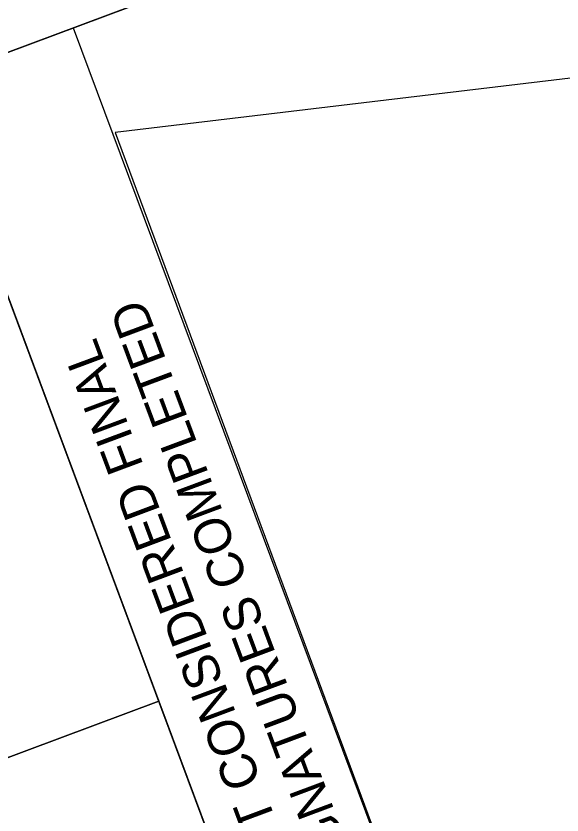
# Model space of a CAD drawing. Extents: x 477774 to 479389, y 493760 to 495720.
# Drawn here: x 477955.2 to 478037.9, y 495270.7 to 495391.6 of the extents above; entities that cross this region are included whole.
import ezdxf

# ---------------------------------------------------------------- set-up
doc = ezdxf.new("R2010")
doc.units = 0
for name, color, linetype in [('Sheet Clip Boundary CELL', 7, 'Continuous'), ('Sheet Plan CELL', 7, 'Continuous'), ('Sheet Sticker Exception Certification CELL', 7, 'Continuous')]:
    doc.layers.add(name, color=color, linetype=linetype)

msp = doc.modelspace()

# ---------------------------------------------------------------- linework, layer by layer
at = {"layer": 'Sheet Clip Boundary CELL'}
msp.add_lwpolyline([(478513.92, 493994.03), (478682.91, 494117.93), (478968.98, 494336.48), (479221.09, 494528.01), (478936.81, 495289.59), (478873.03, 495265.78), (478780.85, 495512.74), (478769.67, 495508.56), (478559.23, 495460.97), (478204.1, 495401.95), (477970.22, 495374), (478033.83, 495202.43), (477871.23, 495141.73), (478325.87, 493923.83)], close=True, dxfattribs=at)
at = {"layer": 'Sheet Plan CELL'}
msp.add_line((477871.45, 495248.6), (477976.8, 495287.94), dxfattribs=at)
for points in [[(477801.28, 495329.17), (478325.84, 493923.85), (479309.54, 494291.03), (478784.99, 495696.34)], [(479309.54, 494291.03), (478325.87, 493923.83), (477871.23, 495141.73), (478011.81, 495194.22), (477941.87, 495381.63), (478784.99, 495696.34)], [(477871.45, 495248.6), (477836.47, 495342.27), (477941.87, 495381.63), (477976.85, 495287.95)], [(477906.43, 495154.87), (477871.45, 495248.6), (477976.85, 495287.95), (478011.81, 495194.22)]]:
    msp.add_lwpolyline(points, close=True, dxfattribs=at)
at = {"layer": 'Sheet Sticker Exception Certification CELL'}
for p, q in [((477941.87, 495381.63), (477963.89, 495389.85)), ((477941.87, 495381.63), (477963.89, 495389.85)), ((477963.88, 495389.84), (478033.83, 495202.43)), ((477963.88, 495389.84), (478033.83, 495202.43)), ((478011.81, 495194.22), (477941.86, 495381.62)), ((478011.81, 495194.22), (477941.86, 495381.62))]:
    msp.add_line(p, q, dxfattribs=at)

# ---------------------------------------------------------------- texts
for s, p in [('UNLESS ALL SIGNATURES COMPLETED', (478024.16, 495215.9)), ('UNLESS ALL SIGNATURES COMPLETED', (478024.16, 495215.9)), ('DOCUMENT NOT CONSIDERED FINAL', (478014.14, 495217.57)), ('DOCUMENT NOT CONSIDERED FINAL', (478014.14, 495217.57))]:
    msp.add_text(s, height=5.5, rotation=110.469, dxfattribs=at).set_placement(p)

doc.saveas('drawing.dxf')
